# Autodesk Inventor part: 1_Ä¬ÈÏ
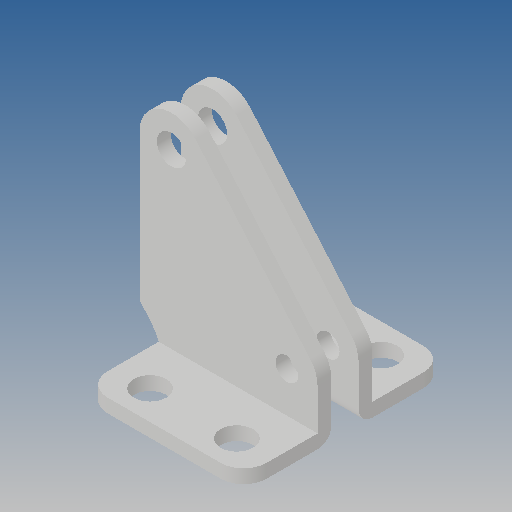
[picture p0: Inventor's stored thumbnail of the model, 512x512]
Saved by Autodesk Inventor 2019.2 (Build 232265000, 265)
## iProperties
Created: 2010-06
Part Number: 1_Ä¬ÈÏ
Material: Ogólny
Document SubType Name: Modeling
Designer: CADENGINEERING4
Density: 1 g/cm^3
Appearance: Domyślna
Author: CADENGINEERING4
Revision Number: ÈÎºÎ
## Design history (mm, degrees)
feature "NONE"
feature "NONE:1"
node "Bryła1"
node "Bryła2"
